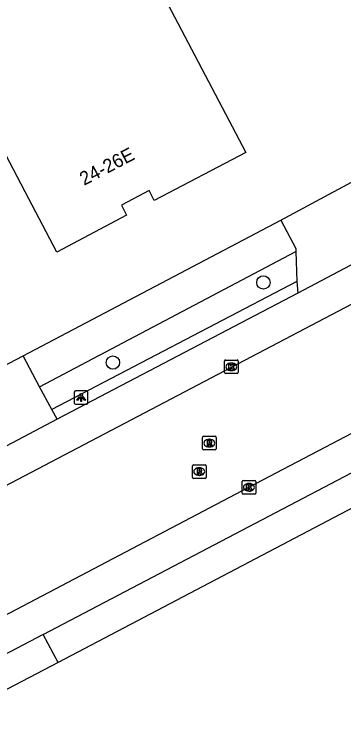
# Model space of a CAD drawing. Extents: x 157692 to 159670, y 381454 to 383289.
# Drawn here: x 158323.1 to 158347.4, y 381827.3 to 381878.9 of the extents above; entities that cross this region are included whole.
import ezdxf

# ---------------------------------------------------------------- set-up
doc = ezdxf.new("R2010")
doc.units = 0
for name, color, linetype in [('IMGEO_Boom', 7, 'Continuous'), ('IMGEO_Kolk', 7, 'Continuous'), ('IMGEO_Lichtpunt', 7, 'Continuous'), ('IMGEO_Pand', 7, 'Continuous'), ('IMGEO_Pand_nummerreeks', 7, 'Continuous'), ('IMGEO_Rijbaan_lokaal_gesloten', 7, 'Continuous'), ('IMGEO_Rijbaan_lokaal_open', 7, 'Continuous'), ('IMGEO_Rioolput', 7, 'Continuous'), ('IMGEO_Voetpad_open', 7, 'Continuous')]:
    doc.layers.add(name, color=color, linetype=linetype)

msp = doc.modelspace()

# ---------------------------------------------------------------- linework, layer by layer
at = {"layer": 'IMGEO_Boom'}
for centre in [(158341.466, 381859.173), (158330.402, 381853.285)]:
    msp.add_circle(centre, 0.489, dxfattribs=at)
at = {"layer": 'IMGEO_Kolk'}
for p, q in [((158338.61, 381852.548), (158338.61, 381853.4)), ((158338.685, 381853.474), (158339.537, 381853.474)), ((158339.098, 381853.254), (158339.123, 381853.254)), ((158339.611, 381853.4), (158339.611, 381852.548)), ((158339.121, 381852.694), (158339.096, 381852.694)), ((158339.537, 381852.474), (158338.685, 381852.474)), ((158339.904, 381843.693), (158339.904, 381844.545)), ((158339.979, 381844.619), (158340.831, 381844.619)), ((158340.392, 381844.399), (158340.417, 381844.399)), ((158340.905, 381844.545), (158340.905, 381843.693)), ((158340.831, 381843.619), (158339.979, 381843.619)), ((158340.415, 381843.839), (158340.39, 381843.839))]:
    msp.add_line(p, q, dxfattribs=at)
for points in [[(158338.61, 381852.548), (158338.61, 381853.4)], [(158338.685, 381853.474), (158339.537, 381853.474)], [(158338.931, 381853.174), (158339.054, 381853.174), (158339.054, 381853.023), (158339.184, 381853.174), (158339.348, 381853.174), (158339.202, 381853.023), (158339.355, 381852.774), (158339.203, 381852.774), (158339.118, 381852.938), (158339.054, 381852.871), (158339.054, 381852.774), (158338.931, 381852.774), (158338.931, 381853.174)], [(158339.611, 381853.4), (158339.611, 381852.548)], [(158339.537, 381852.474), (158338.685, 381852.474)], [(158339.904, 381843.693), (158339.904, 381844.545)], [(158339.979, 381844.619), (158340.831, 381844.619)], [(158340.905, 381844.545), (158340.905, 381843.693)], [(158340.225, 381844.319), (158340.348, 381844.319), (158340.348, 381844.168), (158340.478, 381844.319), (158340.642, 381844.319), (158340.496, 381844.168), (158340.649, 381843.919), (158340.497, 381843.919), (158340.412, 381844.083), (158340.348, 381844.016), (158340.348, 381843.919), (158340.225, 381843.919), (158340.225, 381844.319)], [(158340.831, 381843.619), (158339.979, 381843.619)]]:
    msp.add_lwpolyline(points, dxfattribs=at)
for centre, start, end in [((158338.687, 381853.398), 91.552, 178.448), ((158338.687, 381853.398), 91.552, 178.448), ((158339.535, 381853.398), 1.552, 88.448), ((158339.535, 381853.398), 1.552, 88.448), ((158338.687, 381852.55), 181.552, 268.448), ((158338.687, 381852.55), 181.552, 268.448), ((158339.535, 381852.55), 271.552, 358.448), ((158339.535, 381852.55), 271.552, 358.448), ((158339.981, 381844.543), 91.552, 178.448), ((158339.981, 381844.543), 91.552, 178.448), ((158340.829, 381844.543), 1.552, 88.448), ((158340.829, 381844.543), 1.552, 88.448), ((158339.981, 381843.695), 181.552, 268.448), ((158339.981, 381843.695), 181.552, 268.448), ((158340.829, 381843.695), 271.552, 358.448), ((158340.829, 381843.695), 271.552, 358.448)]:
    msp.add_arc(centre, 0.0765, start, end, dxfattribs=at)
for centre, major_axis, ratio, start_param, end_param in [((158339.097, 381852.974), (-0.387, 0.002), 0.722429, 4.712389, 7.853982), ((158339.122, 381852.974), (-0.39, 0.002), 0.717154, 1.570796, 4.712389), ((158340.391, 381844.119), (-0.387, 0.002), 0.722429, 4.712389, 7.853982), ((158340.416, 381844.119), (-0.39, 0.002), 0.717154, 1.570796, 4.712389)]:
    msp.add_ellipse(centre, major_axis=major_axis, ratio=ratio, start_param=start_param, end_param=end_param, dxfattribs=at)
at = {"layer": 'IMGEO_Lichtpunt'}
for p, q in [((158327.561, 381851.119), (158327.561, 381850.312)), ((158327.561, 381851.119), (158327.561, 381850.312)), ((158328.463, 381851.214), (158327.655, 381851.214)), ((158328.463, 381851.214), (158327.655, 381851.214)), ((158328.557, 381850.312), (158328.557, 381851.119)), ((158328.557, 381850.312), (158328.557, 381851.119)), ((158327.655, 381850.218), (158328.463, 381850.218)), ((158327.655, 381850.218), (158328.463, 381850.218))]:
    msp.add_line(p, q, dxfattribs=at)
for points in [[(158327.935, 381850.783), (158327.974, 381850.755), (158327.786, 381850.493), (158327.748, 381850.52), (158327.935, 381850.783)], [(158328.037, 381850.735), (158328.084, 381850.735), (158328.084, 381850.413), (158328.037, 381850.413), (158328.037, 381850.735)], [(158328.147, 381850.755), (158328.185, 381850.782), (158328.372, 381850.52), (158328.333, 381850.492), (158328.147, 381850.755)]]:
    msp.add_lwpolyline(points, dxfattribs=at)
msp.add_circle((158328.06, 381850.917), 0.0994, dxfattribs=at)
for centre, start, end in [((158327.655, 381851.119), 90, 180), ((158327.655, 381851.119), 90, 180), ((158328.463, 381851.119), 0, 90), ((158328.463, 381851.119), 0, 90), ((158327.655, 381850.312), 180, 270), ((158327.655, 381850.312), 180, 270), ((158328.463, 381850.312), 270, 0), ((158328.463, 381850.312), 270, 360)]:
    msp.add_arc(centre, 0.0946, start, end, dxfattribs=at)
at = {"layer": 'IMGEO_Pand'}
msp.add_lwpolyline([(158333.425, 381881.552), (158340.173, 381868.726), (158333.445, 381865.185), (158333.06, 381865.918), (158331.024, 381864.849), (158331.41, 381864.114), (158326.268, 381861.408), (158323.944, 381865.836), (158319.391, 381874.508), (158321.413, 381875.583), (158309.292, 381898.698)], dxfattribs=at)
at = {"layer": 'IMGEO_Rijbaan_lokaal_gesloten'}
for points in [[(158275.635, 381819.726), (158303.732, 381834.411), (158354.339, 381860.942), (158456.473, 381914.515), (158458.149, 381915.386), (158462.356, 381917.596)], [(158287.161, 381816.195), (158340.401, 381844.12), (158462.964, 381908.32), (158465.398, 381909.602)]]:
    msp.add_lwpolyline(points, dxfattribs=at)
at = {"layer": 'IMGEO_Rijbaan_lokaal_open'}
for points in [[(158342.759, 381863.76), (158347.941, 381866.531)], [(158342.759, 381863.76), (158343.852, 381861.677), (158343.859, 381861.437)], [(158352.126, 381862.671), (158343.994, 381858.396)], [(158343.859, 381861.437), (158343.927, 381859.236)], [(158343.927, 381859.236), (158343.994, 381858.396)], [(158316.773, 381850.116), (158323.795, 381853.778)], [(158325.004, 381851.493), (158323.795, 381853.778)], [(158325.902, 381849.831), (158325.004, 381851.493)], [(158326.305, 381849.121), (158325.902, 381849.831)], [(158326.305, 381849.121), (158319.191, 381845.384)]]:
    msp.add_lwpolyline(points, dxfattribs=at)
at = {"layer": 'IMGEO_Rioolput'}
for p, q in [((158336.989, 381846.94), (158336.989, 381847.792)), ((158337.064, 381847.866), (158337.916, 381847.866)), ((158337.477, 381847.646), (158337.502, 381847.646)), ((158337.99, 381847.792), (158337.99, 381846.94)), ((158337.5, 381847.086), (158337.475, 381847.086)), ((158337.916, 381846.866), (158337.064, 381846.866)), ((158336.251, 381844.846), (158336.251, 381845.698)), ((158336.326, 381845.772), (158337.178, 381845.772)), ((158336.739, 381845.552), (158336.764, 381845.552)), ((158337.252, 381845.698), (158337.252, 381844.846)), ((158336.762, 381844.992), (158336.737, 381844.992)), ((158337.178, 381844.772), (158336.326, 381844.772))]:
    msp.add_line(p, q, dxfattribs=at)
for points in [[(158336.989, 381846.94), (158336.989, 381847.792)], [(158337.064, 381847.866), (158337.916, 381847.866)], [(158337.578, 381847.564), (158337.326, 381847.566), (158337.326, 381847.166)], [(158337.99, 381847.792), (158337.99, 381846.94)], [(158337.326, 381847.166), (158337.45, 381847.166), (158337.45, 381847.328), (158337.461, 381847.328)], [(158337.504, 381847.485), (158337.45, 381847.485), (158337.45, 381847.404)], [(158337.45, 381847.404), (158337.502, 381847.404)], [(158337.508, 381847.299), (158337.579, 381847.166), (158337.719, 381847.166), (158337.654, 381847.292)], [(158337.916, 381846.866), (158337.064, 381846.866)], [(158336.251, 381844.846), (158336.251, 381845.698)], [(158336.326, 381845.772), (158337.178, 381845.772)], [(158336.84, 381845.47), (158336.588, 381845.472), (158336.588, 381845.072)], [(158337.252, 381845.698), (158337.252, 381844.846)], [(158336.588, 381845.072), (158336.712, 381845.072), (158336.712, 381845.234), (158336.723, 381845.234)], [(158336.766, 381845.391), (158336.712, 381845.391), (158336.712, 381845.31)], [(158336.712, 381845.31), (158336.764, 381845.31)], [(158336.77, 381845.205), (158336.841, 381845.072), (158336.981, 381845.072), (158336.916, 381845.198)], [(158337.178, 381844.772), (158336.326, 381844.772)]]:
    msp.add_lwpolyline(points, dxfattribs=at)
for centre, radius, start, end in [((158337.066, 381847.79), 0.0765, 91.552, 178.448), ((158337.066, 381847.79), 0.0765, 91.552, 178.448), ((158337.577, 381847.454), 0.109, 350.3612, 89.416), ((158337.914, 381847.79), 0.0765, 1.552, 88.448), ((158337.914, 381847.79), 0.0765, 1.552, 88.448), ((158337.46, 381847.275), 0.0533, 26.0293, 88.6989), ((158337.486, 381847.593), 0.19, 274.7715, 282.9687), ((158337.51, 381847.389), 0.0964, 77.0061, 93.1865), ((158337.524, 381847.446), 0.0378, 276.6634, 79.6772), ((158337.575, 381847.454), 0.112, 277.5842, 350.9817), ((158337.559, 381847.239), 0.108, 29.5134, 73.7905), ((158337.066, 381846.942), 0.0765, 181.552, 268.448), ((158337.066, 381846.942), 0.0765, 181.552, 268.448), ((158337.914, 381846.942), 0.0765, 271.552, 358.448), ((158337.914, 381846.942), 0.0765, 271.552, 358.448), ((158336.328, 381845.696), 0.0765, 91.552, 178.448), ((158336.328, 381845.696), 0.0765, 91.552, 178.448), ((158336.839, 381845.36), 0.109, 350.3612, 89.416), ((158337.176, 381845.696), 0.0765, 1.552, 88.448), ((158337.176, 381845.696), 0.0765, 1.552, 88.448), ((158336.722, 381845.181), 0.0533, 26.0293, 88.6989), ((158336.748, 381845.499), 0.19, 274.7715, 282.9687), ((158336.772, 381845.295), 0.0964, 77.0061, 93.1865), ((158336.786, 381845.352), 0.0378, 276.6634, 79.6772), ((158336.837, 381845.36), 0.112, 277.5842, 350.9817), ((158336.821, 381845.145), 0.108, 29.5134, 73.7905), ((158336.328, 381844.848), 0.0765, 181.552, 268.448), ((158336.328, 381844.848), 0.0765, 181.552, 268.448), ((158337.176, 381844.848), 0.0765, 271.552, 358.448), ((158337.176, 381844.848), 0.0765, 271.552, 358.448)]:
    msp.add_arc(centre, radius, start, end, dxfattribs=at)
for centre, major_axis, ratio, start_param, end_param in [((158337.476, 381847.366), (-0.387, 0.002), 0.722429, 4.712389, 7.853982), ((158337.501, 381847.366), (-0.39, 0.002), 0.717154, 1.570796, 4.712389), ((158336.738, 381845.272), (-0.387, 0.002), 0.722429, 4.712389, 7.853982), ((158336.763, 381845.272), (-0.39, 0.002), 0.717154, 1.570796, 4.712389)]:
    msp.add_ellipse(centre, major_axis=major_axis, ratio=ratio, start_param=start_param, end_param=end_param, dxfattribs=at)
at = {"layer": 'IMGEO_Voetpad_open'}
for points in [[(158323.795, 381853.778), (158342.759, 381863.76)], [(158325.004, 381851.493), (158343.859, 381861.437)], [(158343.927, 381859.236), (158325.902, 381849.831)], [(158343.994, 381858.396), (158326.305, 381849.121)], [(158325.276, 381833.312), (158361.043, 381852.051)], [(158362.112, 381850.005), (158326.367, 381831.251)], [(158325.276, 381833.312), (158319.401, 381830.234)], [(158326.367, 381831.251), (158325.276, 381833.312)], [(158326.367, 381831.251), (158320.477, 381828.192)]]:
    msp.add_lwpolyline(points, dxfattribs=at)

# ---------------------------------------------------------------- texts
at = {"layer": 'IMGEO_Pand_nummerreeks'}
msp.add_text('24-26E', height=1, rotation=27.6152, dxfattribs=at).set_placement((158328.275, 381866.264))

doc.saveas('drawing.dxf')
